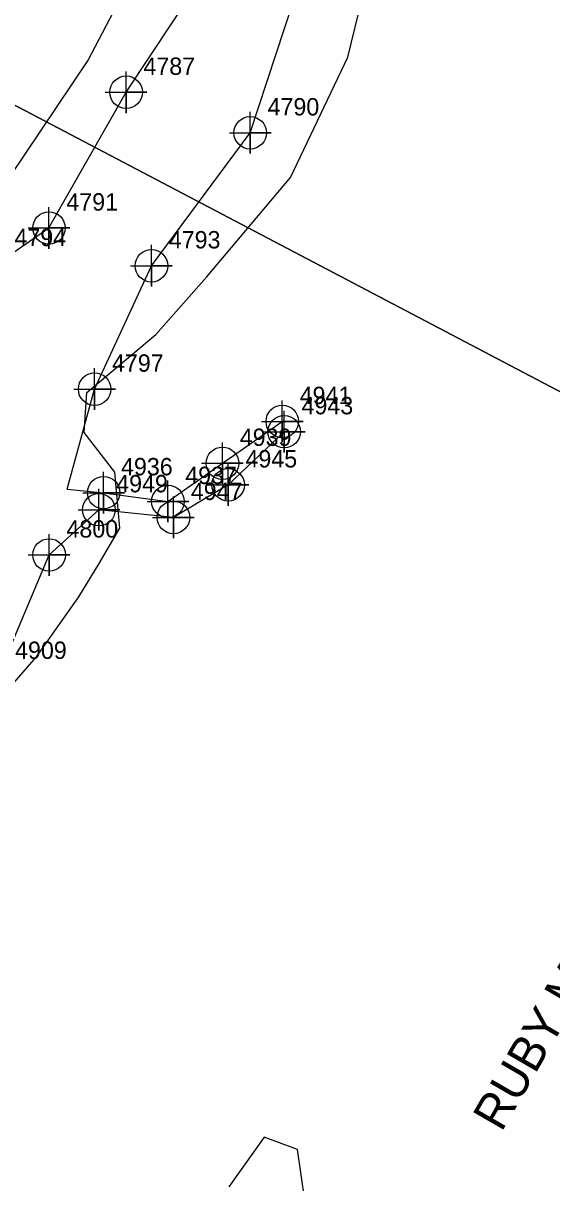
# Model space of a CAD drawing. Extents: x 1653123 to 1656194, y 596584 to 600233.
# Drawn here: x 1653734.2 to 1653810.3, y 597710.9 to 597877.9 of the extents above; entities that cross this region are included whole.
import ezdxf

# ---------------------------------------------------------------- set-up
doc = ezdxf.new("R2010")
doc.units = 0
for name, color, linetype in [('Exist Hydro Jurisdictional Stream or Body of Water', 7, 'Continuous'), ('Exist Hydro Stream or Body of Water Cogo Number', 7, 'Continuous'), ('Exist Property Owner Text', 7, 'Continuous'), ('Exist Right of Way Line', 7, 'Continuous'), ('Exist Vegetation Woods Line', 7, 'Continuous'), ('Prop Easement Construction Station Offsets', 7, 'Continuous'), ('Prop Guardrail', 7, 'Continuous'), ('Prop Guardrail Anchor Unit CELL', 7, 'Continuous')]:
    doc.layers.add(name, color=color, linetype=linetype)

msp = doc.modelspace()

# ---------------------------------------------------------------- linework, layer by layer
at = {"layer": 'Exist Hydro Jurisdictional Stream or Body of Water'}
for points in [[(1653740.51, 597810.78), (1653744.47, 597825.19), (1653752.65, 597842.94), (1653766.87, 597862.08), (1653774.24, 597884.58), (1653779.21, 597901.22), (1653784.8, 597926.15), (1653788.22, 597952.97), (1653784.15, 597976.2), (1653781.49, 597999.08), (1653770.03, 598016.7), (1653766.04, 598023.92)], [(1653703.81, 597789.23), (1653711.98, 597793.87), (1653718.16, 597799.38), (1653723.66, 597804.09), (1653724.22, 597826.08), (1653730.43, 597843.27), (1653737.9, 597848.38), (1653749, 597867.92), (1653762.46, 597888.24), (1653771.7, 597908), (1653776.11, 597927.83), (1653775.18, 597952.39), (1653772.63, 597974.68), (1653768.36, 597994.45), (1653761.04, 598003.47), (1653757.33, 598006.27), (1653756.65, 598007.49)], [(1653717.81, 597771.34), (1653730.52, 597783.85), (1653737.92, 597801.32)]]:
    msp.add_lwpolyline(points, dxfattribs=at)
at = {"layer": 'Exist Right of Way Line'}
msp.add_arc((1655696.35, 596851.16), 2240, 149.9451, 159.30371, dxfattribs=at)
at = {"layer": 'Exist Vegetation Woods Line'}
for points in [[(1653772.69, 597855.66), (1653780.91, 597872.98), (1653787.83, 597901.29), (1653791.96, 597923.72), (1653796.55, 597945.52), (1653799.73, 597979.56), (1653801.79, 597996.22), (1653796.29, 598010.03), (1653789.11, 598020.31), (1653789.79, 598024.53), (1653810.3, 598062.92), (1653854.44, 598139.76), (1653881.65, 598185.93), (1653890.13, 598190.27), (1653890.78, 598172.44), (1653888.25, 598125.23), (1653881.52, 598039.21), (1653880.39, 597979.92), (1653882.93, 597907.14), (1653887.55, 597812.44), (1653892.77, 597769.35), (1653892.8, 597738.52)], [(1653717.51, 597885.35), (1653754.38, 597956.02), (1653763.96, 597955.58), (1653764.6, 597948.91), (1653757.42, 597915.01), (1653754.23, 597900.42), (1653752.18, 597889.08), (1653743.53, 597872.59)], [(1653743.53, 597872.59), (1653727.72, 597849.07), (1653722.44, 597840.57), (1653717.66, 597833.58), (1653714.51, 597826.4), (1653715.63, 597812.68), (1653715.73, 597807.63), (1653713.11, 597803.16), (1653698.27, 597795.72), (1653684.13, 597803.11), (1653677.18, 597807.18), (1653678.58, 597812.27), (1653717.51, 597885.35)], [(1653682.04, 597708.83), (1653688.1, 597712.91), (1653702.08, 597727.65), (1653713.33, 597738.79), (1653717.03, 597745.05), (1653720.88, 597751.65), (1653717.53, 597760.89), (1653720.03, 597771.59), (1653727.67, 597777.01), (1653736.11, 597786.67), (1653742.22, 597795.29), (1653745.11, 597800.08), (1653748.1, 597805.18), (1653747.38, 597813.21), (1653742.97, 597818.93), (1653743.36, 597824.69), (1653753.29, 597833.05), (1653760.6, 597841.3), (1653772.69, 597855.66)], [(1653774.75, 597708.46), (1653773.66, 597715.73), (1653768.88, 597717.51), (1653763.81, 597710.37)]]:
    msp.add_lwpolyline(points, dxfattribs=at)
at = {"layer": 'Prop Easement Construction Station Offsets'}
for points in [[(1653740.51, 597810.78), (1653745.77, 597810.28), (1653755.02, 597809.02), (1653762.87, 597814.51), (1653771.49, 597820.53)], [(1653771.76, 597819.06), (1653763.69, 597811.41), (1653755.82, 597806.72), (1653745.08, 597807.83), (1653737.92, 597801.32)]]:
    msp.add_lwpolyline(points, dxfattribs=at)
at = {"layer": 'Prop Guardrail'}
for points in [[(1653903.59, 597776.41), (1653711.71, 597877.2), (1653696.02, 597886.41), (1653672.02, 597900.5), (1653657.82, 597908.84), (1653581.92, 597953.42), (1653467.13, 598020.82), (1653530, 598138.71), (1653544.59, 598164.59), (1653608.47, 598270), (1653650, 598338.52), (1653727.49, 598470), (1653919.05, 598343.12), (1654024.03, 598279.05), (1654101.16, 598231.66), (1654152.92, 598207.08), (1653974.95, 597910)], [(1653467.13, 598020.82), (1653523.07, 597987.98), (1653581.92, 597953.42), (1653657.82, 597908.84), (1653672.02, 597900.5), (1653696.02, 597886.41), (1653711.71, 597877.2), (1653903.59, 597776.41), (1653848.79, 597671.21), (1653796.49, 597523.51), (1653747.41, 597390), (1653709.73, 597290.27), (1653571.5, 597363.59), (1653527.51, 597387.98), (1653462.99, 597422.58), (1653451.94, 597428.93), (1653267.19, 597532.81), (1653332.24, 597710), (1653352.48, 597767.52), (1653388.58, 597870)]]:
    msp.add_lwpolyline(points, close=True, dxfattribs=at)
at = {"layer": 'Prop Guardrail Anchor Unit CELL'}
for points in [[(1653746, 597867.92), (1653752, 597867.92), (1653749, 597867.92), (1653749, 597864.92), (1653749, 597870.92)], [(1653763.87, 597862.08), (1653769.87, 597862.08), (1653766.87, 597862.08), (1653766.87, 597859.08), (1653766.87, 597865.08)], [(1653734.9, 597848.38), (1653740.9, 597848.38), (1653737.9, 597848.38), (1653737.9, 597845.38), (1653737.9, 597851.38)], [(1653749.65, 597842.94), (1653755.65, 597842.94), (1653752.65, 597842.94), (1653752.65, 597839.94), (1653752.65, 597845.94)], [(1653741.47, 597825.19), (1653747.47, 597825.19), (1653744.47, 597825.19), (1653744.47, 597822.19), (1653744.47, 597828.19)], [(1653768.49, 597820.53), (1653774.49, 597820.53), (1653771.49, 597820.53), (1653771.49, 597817.53), (1653771.49, 597823.53)], [(1653768.76, 597819.06), (1653774.76, 597819.06), (1653771.76, 597819.06), (1653771.76, 597816.06), (1653771.76, 597822.06)], [(1653759.87, 597814.51), (1653765.87, 597814.51), (1653762.87, 597814.51), (1653762.87, 597811.51), (1653762.87, 597817.51)], [(1653760.69, 597811.41), (1653766.69, 597811.41), (1653763.69, 597811.41), (1653763.69, 597808.41), (1653763.69, 597814.41)], [(1653742.77, 597810.28), (1653748.77, 597810.28), (1653745.77, 597810.28), (1653745.77, 597807.28), (1653745.77, 597813.28)], [(1653752.02, 597809.02), (1653758.02, 597809.02), (1653755.02, 597809.02), (1653755.02, 597806.02), (1653755.02, 597812.02)], [(1653742.08, 597807.83), (1653748.08, 597807.83), (1653745.08, 597807.83), (1653745.08, 597804.83), (1653745.08, 597810.83)], [(1653752.82, 597806.72), (1653758.82, 597806.72), (1653755.82, 597806.72), (1653755.82, 597803.72), (1653755.82, 597809.72)], [(1653734.92, 597801.32), (1653740.92, 597801.32), (1653737.92, 597801.32), (1653737.92, 597798.32), (1653737.92, 597804.32)]]:
    msp.add_lwpolyline(points, dxfattribs=at)
for centre in [(1653749, 597867.92), (1653766.87, 597862.08), (1653737.9, 597848.38), (1653752.65, 597842.94), (1653744.47, 597825.19), (1653771.49, 597820.53), (1653771.76, 597819.06), (1653762.87, 597814.51), (1653763.69, 597811.41), (1653745.77, 597810.28), (1653745.08, 597807.83), (1653755.02, 597809.02), (1653755.82, 597806.72), (1653737.92, 597801.32)]:
    msp.add_circle(centre, 2.34, dxfattribs=at)

# ---------------------------------------------------------------- texts
at = {"layer": 'Exist Hydro Stream or Body of Water Cogo Number'}
for s, p in [('4787', (1653751.5, 597870.42)), ('4790', (1653769.37, 597864.58)), ('4791', (1653740.4, 597850.88)), ('4794', (1653732.93, 597845.77)), ('4793', (1653755.15, 597845.44)), ('4797', (1653746.97, 597827.69)), ('4941', (1653773.99, 597823.03)), ('4943', (1653774.26, 597821.56)), ('4939', (1653765.37, 597817.01)), ('4936', (1653748.27, 597812.78)), ('4945', (1653766.19, 597813.91)), ('4937', (1653757.52, 597811.52)), ('4949', (1653747.58, 597810.33)), ('4947', (1653758.32, 597809.22)), ('4800', (1653740.42, 597803.82)), ('4909', (1653733.02, 597786.35))]:
    msp.add_text(s, height=2.5, dxfattribs=at).set_placement(p)
at = {"layer": 'Exist Property Owner Text'}
msp.add_text('RUBY M. ALMOND, ESTATE', height=5, rotation=59.9255, dxfattribs=at).set_placement((1653803.04, 597718.13))

doc.saveas('drawing.dxf')
